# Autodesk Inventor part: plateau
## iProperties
Author: robert
Shininess: 21.0
PropertySet Name: _Private Model Information
Compacted: True
Length Units: 11269
Angle Units: 11283
Time Units: 11279
Mass Units: 11290
Length Display Precision: 3
Angle Display Precision: 2
Created: 2001-07
Part Number: plateau
Material: Par défaut
Document SubType Name: Modélisation
Designer: robert
Control State: 0
Master: False
Checked Out: False
PropertySet Name: Design Tracking Control
Density: 0.0
Volumn: 0.0
Area: 0.0
PropertySet Name: Model Information
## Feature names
1. Révolution1 [Revolution]
2. Révolution2 [Revolution]
3. Extrusion1
4. Perçage1 [Hole]
5. Extrusion2
6. Congé1 [Fillet]
7. Congé2 [Fillet]
8. Congé3 [Fillet]
9. Congé4 [Fillet]
10. Congé5 [Fillet]
